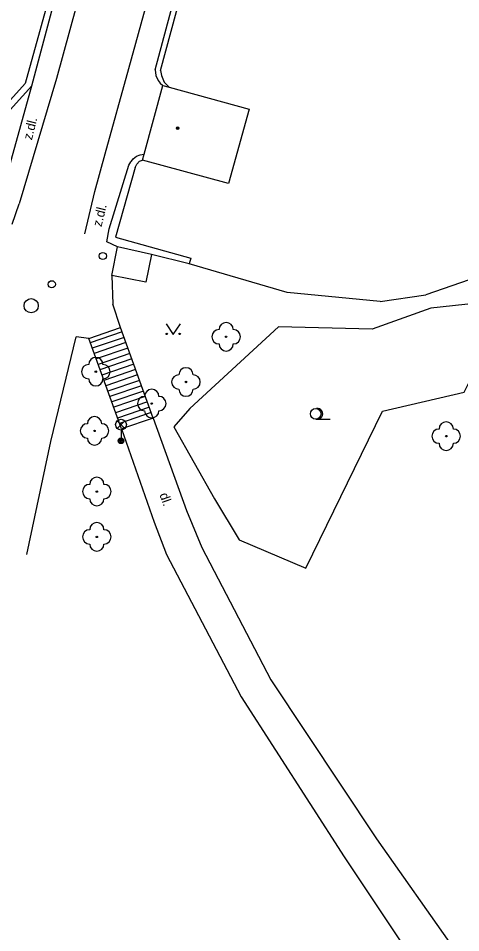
# Model space of a CAD drawing. Extents: x -600391 to -599491, y -1160176 to -1159402.
# Drawn here: x -599887.9 to -599857, y -1159537.3 to -1159473.4 of the extents above; entities that cross this region are included whole.
import ezdxf

# ---------------------------------------------------------------- set-up
doc = ezdxf.new("R2010")
doc.units = 0
for name, color, linetype in [('Level 10', 7, 'Continuous'), ('Level 11', 7, 'Continuous'), ('Level 21', 7, 'Continuous'), ('Level 22', 7, 'Continuous'), ('Level 27', 7, 'Continuous'), ('Level 28', 7, 'Continuous'), ('Level 31', 7, 'Continuous'), ('Level 33', 7, 'Continuous'), ('Level 36', 7, 'Continuous'), ('Level 39', 7, 'Continuous'), ('Level 40', 7, 'Continuous'), ('Level 5', 7, 'Continuous'), ('Level 7', 7, 'Continuous')]:
    doc.layers.add(name, color=color, linetype=linetype)

msp = doc.modelspace()

# ---------------------------------------------------------------- linework, layer by layer
at = {"layer": 'Level 10'}
for points in [[(-599864.409, -1159401.769), (-599866.57, -1159409.56), (-599880, -1159458.36), (-599880.74, -1159461.06), (-599885.28, -1159477.58), (-599887.88, -1159486.35)], [(-599864.409, -1159401.769), (-599866.57, -1159409.56), (-599880, -1159458.36), (-599880.74, -1159461.06), (-599885.28, -1159477.58), (-599887.88, -1159486.35)], [(-599883.3, -1159488.45), (-599882.59, -1159485.48), (-599881.86, -1159482.85), (-599880.21, -1159476.88), (-599871.91, -1159446.81), (-599870.84, -1159442.92), (-599861.45, -1159409.16), (-599859.365, -1159401.769)], [(-599883.3, -1159488.45), (-599882.59, -1159485.48), (-599881.86, -1159482.85), (-599880.21, -1159476.88), (-599871.91, -1159446.81), (-599870.84, -1159442.92), (-599861.45, -1159409.16), (-599859.365, -1159401.769)], [(-599888.37, -1159487.77), (-599887.88, -1159486.35)]]:
    msp.add_lwpolyline(points, dxfattribs=at)
at = {"layer": 'Level 11'}
for points in [[(-599889.18, -1159485.99), (-599887, -1159478.09)], [(-599889.18, -1159485.99), (-599887, -1159478.09)], [(-599878.62, -1159489.88), (-599879.02, -1159491.81)], [(-599878.62, -1159489.88), (-599879.02, -1159491.81)], [(-599881.39, -1159491.36), (-599881.34, -1159493.37)], [(-599878.51, -1159501.32), (-599880.8, -1159495), (-599881.34, -1159493.37)], [(-599883.01, -1159495.77), (-599880.8, -1159495)], [(-599880.69, -1159495.3), (-599882.91, -1159496.06)], [(-599887.34, -1159510.86), (-599885.66, -1159502.96), (-599883.9, -1159495.65)], [(-599883.01, -1159495.77), (-599883.9, -1159495.65)], [(-599880.73, -1159502.08), (-599883.01, -1159495.77)], [(-599880.55, -1159495.68), (-599882.77, -1159496.44)], [(-599880.42, -1159496.05), (-599882.63, -1159496.81)], [(-599880.28, -1159496.43), (-599882.5, -1159497.19)], [(-599880.15, -1159496.81), (-599882.36, -1159497.57)], [(-599880.01, -1159497.18), (-599882.23, -1159497.94)], [(-599879.87, -1159497.56), (-599882.09, -1159498.32)], [(-599879.74, -1159497.93), (-599881.95, -1159498.69)], [(-599879.6, -1159498.31), (-599881.82, -1159499.07)], [(-599879.46, -1159498.69), (-599881.68, -1159499.45)], [(-599879.33, -1159499.06), (-599881.55, -1159499.82)], [(-599879.19, -1159499.44), (-599881.41, -1159500.2)], [(-599879.06, -1159499.82), (-599881.27, -1159500.57)], [(-599878.92, -1159500.19), (-599881.14, -1159500.95)], [(-599878.78, -1159500.57), (-599881, -1159501.33)], [(-599878.65, -1159500.94), (-599880.87, -1159501.7)], [(-599878.51, -1159501.32), (-599880.73, -1159502.08)], [(-599878.51, -1159501.32), (-599876.18, -1159507.78)], [(-599874.23, -1159506.96), (-599872.49, -1159509.84), (-599867.83, -1159511.83), (-599862.49, -1159500.84)], [(-599880.73, -1159502.08), (-599878.45, -1159508.61)], [(-599876.18, -1159507.78), (-599875.1, -1159510.37), (-599870.28, -1159519.62)], [(-599878.45, -1159508.61), (-599877.58, -1159510.87), (-599872.36, -1159520.82)], [(-599870.28, -1159519.62), (-599862.91, -1159530.75)], [(-599872.36, -1159520.82), (-599865.16, -1159532.01)], [(-599862.91, -1159530.75), (-599857.51, -1159538.4)], [(-599865.16, -1159532.01), (-599859.99, -1159539.76)]]:
    msp.add_lwpolyline(points, dxfattribs=at)
at = {"layer": 'Level 21'}
msp.add_lwpolyline([(-599862.49, -1159500.84), (-599856.77, -1159499.51), (-599854.72, -1159495.41), (-599855, -1159493.2), (-599859.11, -1159493.64), (-599863.2, -1159495.11), (-599869.76, -1159494.95), (-599875.95, -1159500.65), (-599877.07, -1159501.93), (-599874.23, -1159506.96)], dxfattribs=at)
at = {"layer": 'Level 22'}
for centre in [(-599873.41, -1159495.64), (-599882.52, -1159498.08), (-599876.22, -1159498.8), (-599878.61, -1159500.31), (-599882.61, -1159502.22), (-599858.03, -1159502.59), (-599882.45, -1159506.46), (-599882.45, -1159509.63)]:
    msp.add_circle(centre, 0.05, dxfattribs=at)
for centre, start, end in [((-599873.41, -1159495.14), 0, 180), ((-599873.91, -1159495.64), 90, 270), ((-599872.91, -1159495.64), 270, 90), ((-599873.41, -1159496.14), 180, 0), ((-599882.52, -1159497.58), 0, 180), ((-599883.02, -1159498.08), 90, 270), ((-599882.02, -1159498.08), 270, 90), ((-599876.22, -1159498.3), 0, 180), ((-599882.52, -1159498.58), 180, 0), ((-599876.72, -1159498.8), 90, 270), ((-599875.72, -1159498.8), 270, 90), ((-599878.61, -1159499.81), 0, 180), ((-599876.22, -1159499.3), 180, 0), ((-599879.11, -1159500.31), 90, 270), ((-599878.11, -1159500.31), 270, 90), ((-599882.61, -1159501.72), 0, 180), ((-599878.61, -1159500.81), 180, 0), ((-599883.11, -1159502.22), 90, 270), ((-599882.11, -1159502.22), 270, 90), ((-599858.03, -1159502.09), 0, 180), ((-599858.53, -1159502.59), 90, 270), ((-599857.53, -1159502.59), 270, 90), ((-599882.61, -1159502.72), 180, 0), ((-599858.03, -1159503.09), 180, 0), ((-599882.45, -1159505.96), 0, 180), ((-599882.95, -1159506.46), 90, 270), ((-599881.95, -1159506.46), 270, 90), ((-599882.45, -1159506.96), 180, 0), ((-599882.45, -1159509.13), 0, 180), ((-599882.95, -1159509.63), 90, 270), ((-599881.95, -1159509.63), 270, 90), ((-599882.45, -1159510.13), 180, 0)]:
    msp.add_arc(centre, 0.5, start, end, dxfattribs=at)
at = {"layer": 'Level 27'}
msp.add_circle((-599887.04, -1159493.47), 0.5, dxfattribs=at)
at = {"layer": 'Level 28'}
msp.add_circle((-599885.6, -1159491.97), 0.25, dxfattribs=at)
at = {"layer": 'Level 31'}
msp.add_circle((-599882.03, -1159489.99), 0.25, dxfattribs=at)
at = {"layer": 'Level 33'}
for p, q in [((-599881.025, -1159502.05), (-599880.495, -1159501.52)), ((-599881.025, -1159501.52), (-599880.495, -1159502.05)), ((-599880.76, -1159502.16), (-599880.76, -1159502.91))]:
    msp.add_line(p, q, dxfattribs=at)
for centre, radius in [((-599880.76, -1159501.785), 0.375), ((-599880.76, -1159502.91), 0.2), ((-599880.76, -1159502.91), 0.145), ((-599880.76, -1159502.91), 0.0876)]:
    msp.add_circle(centre, radius, dxfattribs=at)
at = {"layer": 'Level 36'}
msp.add_line((-599867.15, -1159501.405), (-599866.15, -1159501.405), dxfattribs=at)
msp.add_lwpolyline([(-599877.61, -1159494.74), (-599877.11, -1159495.49), (-599876.61, -1159494.74)], dxfattribs=at)
for centre, radius in [((-599877.56, -1159495.44), 0.05), ((-599876.661, -1159495.44), 0.05), ((-599867.15, -1159501.03), 0.375)]:
    msp.add_circle(centre, radius, dxfattribs=at)
msp.add_arc((-599867.025, -1159501.03), 0.375, 260.40593, 99.59407, dxfattribs=at)
at = {"layer": 'Level 39'}
for radius in [0.09, 0.0398]:
    msp.add_circle((-599876.8, -1159481.05), radius, dxfattribs=at)
at = {"layer": 'Level 5'}
for points in [[(-599879.15, -1159482.86), (-599877.83, -1159478.07)], [(-599877.83, -1159478.07), (-599877.4, -1159478.19)], [(-599877.4, -1159478.19), (-599871.81, -1159479.72)], [(-599871.81, -1159479.72), (-599873.24, -1159484.93)], [(-599879.26, -1159483.28), (-599879.15, -1159482.86)], [(-599873.24, -1159484.93), (-599879.26, -1159483.28)], [(-599879.02, -1159491.81), (-599881.39, -1159491.36), (-599881.01, -1159489.36)], [(-599878.62, -1159489.88), (-599881.01, -1159489.36)], [(-599878.62, -1159489.88), (-599881.01, -1159489.36)]]:
    msp.add_lwpolyline(points, dxfattribs=at)
at = {"layer": 'Level 7'}
for points in [[(-599878.38, -1159476.97), (-599870.28, -1159446.81), (-599869.35, -1159443.35)], [(-599877.99, -1159477.03), (-599868.91, -1159443.47)], [(-599885.34, -1159470.25), (-599887.46, -1159477.92)], [(-599887, -1159478.09), (-599884.94, -1159470.37)], [(-599878.38, -1159476.97), (-599878.33, -1159477.36), (-599878.17, -1159477.71), (-599878.02, -1159477.91), (-599877.83, -1159478.07)], [(-599877.99, -1159477.03), (-599877.94, -1159477.38), (-599877.74, -1159477.83), (-599877.4, -1159478.19)], [(-599842.21, -1159477.57), (-599845.68, -1159484.12), (-599852.11, -1159490.17), (-599859.46, -1159492.71)], [(-599887.46, -1159477.92), (-599891.58, -1159482.5)], [(-599887, -1159478.09), (-599891.35, -1159482.9)], [(-599880.21, -1159483.65), (-599880.08, -1159483.4), (-599880.03, -1159483.35), (-599879.9, -1159483.19), (-599879.68, -1159483.02), (-599879.42, -1159482.91), (-599879.15, -1159482.86)], [(-599879.77, -1159483.8), (-599879.66, -1159483.56), (-599879.46, -1159483.37), (-599879.26, -1159483.28)], [(-599881.59, -1159488.1), (-599880.21, -1159483.65)], [(-599881.59, -1159488.1), (-599880.21, -1159483.65)], [(-599879.77, -1159483.8), (-599881.15, -1159488.67), (-599875.89, -1159490.14), (-599876, -1159490.55)], [(-599879.77, -1159483.8), (-599881.15, -1159488.67), (-599875.89, -1159490.14), (-599876, -1159490.55)], [(-599881.75, -1159488.99), (-599881.59, -1159488.1)], [(-599881.75, -1159488.99), (-599881.59, -1159488.1)], [(-599881.01, -1159489.36), (-599881.75, -1159488.99)], [(-599881.01, -1159489.36), (-599881.75, -1159488.99)], [(-599876, -1159490.55), (-599878.62, -1159489.88)], [(-599876, -1159490.55), (-599878.62, -1159489.88)], [(-599862.64, -1159493.18), (-599869.14, -1159492.54), (-599876, -1159490.55)], [(-599862.64, -1159493.18), (-599869.14, -1159492.54), (-599876, -1159490.55)], [(-599862.64, -1159493.18), (-599859.46, -1159492.71)], [(-599862.64, -1159493.18), (-599859.46, -1159492.71)]]:
    msp.add_lwpolyline(points, dxfattribs=at)

# ---------------------------------------------------------------- texts
at = {"layer": 'Level 40'}
for s, rotation, p in [('z.dl.', 76, (-599886.99, -1159481.92)), ('z.dl.', 76, (-599882.13, -1159487.99)), ('dl.', 289, (-599878.08, -1159506.67))]:
    msp.add_text(s, height=0.65, rotation=rotation, dxfattribs=at).set_placement(p)

doc.saveas('drawing.dxf')
